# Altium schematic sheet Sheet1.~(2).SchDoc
size A4
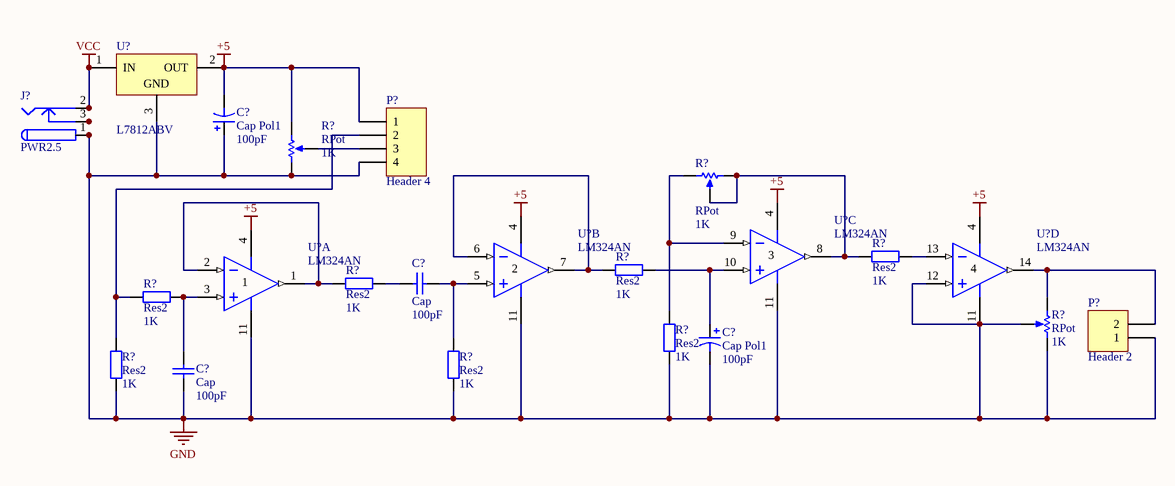
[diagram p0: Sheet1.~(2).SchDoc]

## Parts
(Parts that share a designator on the sheet are numbered #1, #2 ... from top to bottom, then left to right.)
C?#1  Cap Pol1  value 100pF  [RB7.6-15]
C?#2  Cap  value 100pF  [RAD-0.3]
C?#3  Cap Pol1  value 100pF  [RB7.6-15]
C?#4  Cap  value 100pF  [RAD-0.3]
J?  PWR2.5  [KLD-0202]
P?#1  Header 4  [HDR1X4]
P?#2  Header 2  [HDR1X2]
R?#1  RPot  value 1K  [VR5]
R?#2  RPot  value 1K  [VR5]
R?#3  Res2  value 1K  [AXIAL-0.4]
R?#4  Res2  value 1K  [AXIAL-0.4]
R?#5  Res2  value 1K  [AXIAL-0.4]
R?#6  Res2  value 1K  [AXIAL-0.4]
R?#7  RPot  value 1K  [VR5]
R?#8  Res2  value 1K  [AXIAL-0.4]
R?#9  Res2  value 1K  [AXIAL-0.4]
R?#10  Res2  value 1K  [AXIAL-0.4]
U?#1  L7812ABV  [TO220ABN]
U?#2  LM324AN  [N14A]  (part C of 4)
U?#3  LM324AN  [N14A]  (part B of 4)
U?#4  LM324AN  [N14A]  (part D of 4)
U?#5  LM324AN  [N14A]  (part A of 4)

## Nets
+5: C?#1.2 P?#1.1 R?#1.2(BOT) U?#1.2(OUT) U?#2.4(V+) U?#3.4(V+) U?#4.4(V+) U?#5.4(V+)
GND: C?#1.1 C?#3.2 C?#4.1 J?.1 J?.1A J?.1B P?#1.4 P?#2.1 R?#1.1(TOP) R?#7.2(BOT) R?#7.3(TAP) R?#8.2 R?#9.2 R?#10.1 U?#1.3(GND) U?#2.11(GND) U?#3.11(GND) U?#4.11(GND) U?#4.12(IN+) U?#5.11(GND)
VCC: J?.2 J?.2A J?.2B U?#1.1(IN)
NetC?#2_1: C?#2.1 R?#9.1 U?#3.5(IN+)
NetC?#2_2: C?#2.2 R?#5.1
NetC?#3_1: C?#3.1 R?#4.1 U?#2.10(IN+)
NetC?#4_2: C?#4.2 R?#6.1 U?#5.3(IN+)
NetJ?_3: J?.3 J?.3A J?.3B
NetP?#1_2: P?#1.2 R?#6.2 R?#10.2
NetP?#1_3: P?#1.3 R?#1.3(TAP)
NetP?#2_2: P?#2.2 R?#7.1(TOP) U?#4.14(OUT)
NetR?#2_1: R?#2.1(TOP) R?#8.1 U?#2.9(IN-)
NetR?#2_2: R?#2.2(BOT) R?#2.3(TAP) R?#3.2 U?#2.8(OUT)
NetR?#3_1: R?#3.1 U?#4.13(IN-)
NetR?#4_2: R?#4.2 U?#3.6(IN-) U?#3.7(OUT)
NetR?#5_2: R?#5.2 U?#5.1(OUT) U?#5.2(IN-)

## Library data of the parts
C?#1 C?#3 = Cap Pol1: Polarized Capacitor (Radial)
C?#2 C?#4 = Cap: Capacitor
J? = PWR2.5: Low Voltage Power Supply Connector
P?#1 = Header 4: Header, 4-Pin
P?#2 = Header 2: Header, 2-Pin
R?#1 R?#2 R?#7 = RPot: Potentiometer; Sim Note: Enter the Resistance value and the set point into parameter fields.; Set Position: 0.5
R?#3-R?#6 R?#8-R?#10 = Res2: Resistor
U?#1 = L7812ABV: Precision 1A Regulator
U?#2-U?#5 = LM324AN: Low-Power Quad Operational Amplifier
